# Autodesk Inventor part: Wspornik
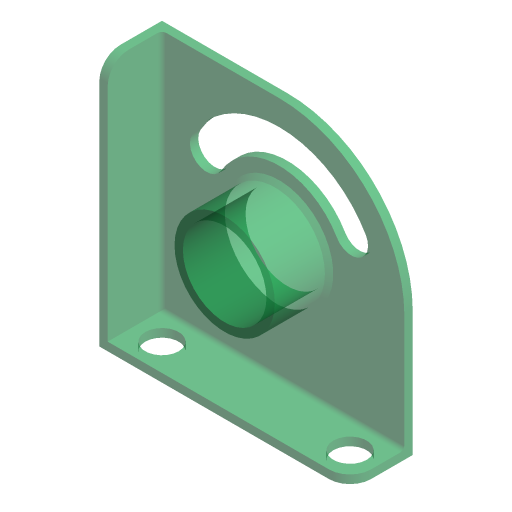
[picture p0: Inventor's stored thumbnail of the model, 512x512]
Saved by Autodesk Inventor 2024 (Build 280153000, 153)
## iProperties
Company: ATC
Shininess: 0.0
Length Units: 11269
Angle Units: 11279
Time Units: 11290
Mass Units: 11283
Length Display Precision: 3
Angle Display Precision: 2
Compacted: True
Created: 2023-03
Part Number: Wspornik
Document SubType Name: Modeling
Designer: Andrzej Jaskulski
Density: 1 g/cm^3
Material: Ogólny
Appearance: Green(Clear)
Checked By: A.J.
Engr Approved By: Andrzej Jaskulski
Mfg Approved By: Andrzej Jaskulski
Authority: A.J.
Density: 0.0
Volumn: 0.0
Area: 0.0
PropertySet Name: Model Information
Control State: 0
Master: False
Checked Out: False
Title: A.J.: Kurs R2024-MEP
Author: Andrzej Jaskulski
Revision Number: 1/24
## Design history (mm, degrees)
node "Extrusion1" dims "d1" = 15, "d2" = 0
node "Hole1" dims "d5" = 20, "d6" = 4, "d7" = 2, "d8" = 60 deg, "d9" = 8, "d10" = 118 deg
node "Fillet1" dims "d12" = 5
node "Fillet2" dims "d13" = 30
node "Shell2" dims "d14" = 2
node "Hole2" dims "d17" = 8, "d18" = 4, "d19" = 2, "d20" = 60 deg, "d21" = 8, "d22" = 118 deg
node "Extrusion2" dims "d28" = 15, "d29" = 0
node "Fillet3" dims "d30" = 1
node "Chamfer1" dims "d31" = 1, "d32" = 1, "d35" = 45 deg
node "Bryła1"
node "Korpusy bryłowe"
node "Korpusy powierzchniowe"
sketch "Sketch1"
  geometry: L1 (0, 0)-(60, 0); L2 (60, 0)-(60, 60); L3 (60, 60)-(0, 60); L4 (0, 60)-(0, 0)
  constraints: 8 end point, 2 parallel, 2 perpendicular, 1 horizontal, 1 other
  dimensions: "d0" = 60 distance of L1.start L1.end
sketch "Sketch3"
  geometry: L1 (0, 0)-(60, 0) reference; L2 (0, 60)-(0, 0) reference; 1 further point
  dimensions: "d3" = 30 distance from line of L1 point (30, 30); "d4" = 30 distance from line of L2 point (30, 30)
sketch "Sketch4"
  geometry: L1 (58, 0)-(58, -8) reference; L2 (0, -13)-(0, 0) reference; L3 (53, -13)-(0, -13) reference; L4 (0, -6.5)-(58, -6.5); 2 further points
  constraints: 3 point on line, 2 end point, 1 midpoint, 1 parallel
  dimensions: "d15" = 6.5 distance from line of L2 point (6.5, -6.5); "d16" = 6.5 distance from line of L1 point (51.5, -6.5); "d33" = 6.5 distance between parallel lines of L3 L4; "d34" = 45 distance of point (51.5, -6.5) point (6.5, -6.5)
sketch "Sketch5"
  geometry: L1 (-30, 60)-(0, 60) reference; L2 (-30, 30)-(-30, 63); C1 r 10 at (-30, 30) reference; A1 r 16 centre (-30, 30) between (-16.144, 38) and (-43.856, 38); A2 r 24 centre (-30, 30) between (-9.215, 42) and (-50.785, 42); A3 r 4 centre (-47.321, 40) between (-50.785, 42) and (-43.856, 38); A4 r 4 centre (-12.679, 40) between (-16.144, 38) and (-9.215, 42)
  constraints: 8 point on circle, 4 centre point, 2 coincident, 2 end point, 2 tangent, 1 perpendicular
  dimensions: "d26" = 16 radius of A1; "d27" = 24 radius of A2
